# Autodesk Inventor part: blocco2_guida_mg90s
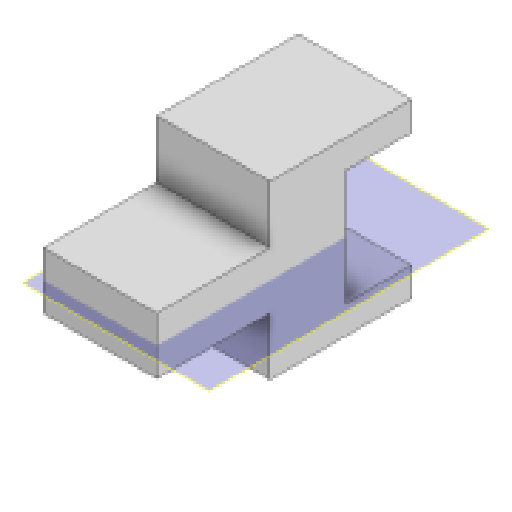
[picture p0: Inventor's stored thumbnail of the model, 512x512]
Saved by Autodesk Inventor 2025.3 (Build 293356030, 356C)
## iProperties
Created: 2026-04
Part Number: blocco2_guida_mg90s
Material: Generico
Document SubType Name: Modeling
Designer: R5800u
Density: 1 g/cm^3
Appearance: Default
Author: R5800u
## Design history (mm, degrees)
sketch "Schizzo1"
  geometry: L1 (-12.6, 12.35)-(-12.6, 0.15) reference; L2 (-2.271, 12.35)-(-2.271, 12.25) reference; L3 (-2.271, 12.25)-(-3.771, 12.25) reference; L4 (-3.771, 12.25)-(-3.771, 12.35) reference; L5 (-9.415, 12.35)-(-3.771, 12.35) reference; L6 (-9.415, 12.35)-(-9.415, 12.25) reference; L7 (-9.415, 12.25)-(-10.915, 12.25) reference; L8 (-10.915, 12.25)-(-10.915, 12.35) reference; L9 (-12.6, 12.35)-(-10.915, 12.35) reference; L10 (-12.6, 12.35)-(-12.6, 0.15) reference; L11 (5.4, 0.15)-(-12.6, 0.15) reference; L12 (5.4, 12.35)-(5.4, 0.15) reference; L13 (-2.271, 12.35)-(5.4, 12.35) reference; L14 (-12.6, 0.15)-(-0.6, 0.15); L15 (-0.6, 0.15)-(-0.6, 12.35); L16 (-0.6, 12.35)-(-12.6, 12.35); L17 (-12.6, 12.35)-(-12.6, 0.15); 12 further points
  constraints: 8 end point, 2 parallel, 1 horizontal, 1 perpendicular
  dimensions: "d0" = 12.2 distance of L15.end L14.end; "d12" = 12 distance of L1.end L14.end
extrude "Estrusione1" new body sketch "Schizzo1" distance "d1" = 8; taper "d2" = 0 deg
sketch "Schizzo3"
  geometry: L1 (-12.6, 12.35)-(-12.6, 0.15) reference; L2 (-12.6, 6.25)-(-3.6, 6.25); L3 (-12.6, 3.25)-(5.4, 3.25); L4 (5.4, 3.25)-(5.4, 9.25); L5 (5.4, 9.25)-(-12.6, 9.25); L6 (-12.6, 9.25)-(-12.6, 3.25); L7 (-0.6, 0.15)-(-0.6, 12.35) reference; 4 further points
  constraints: 10 end point, 2 parallel, 1 horizontal, 1 midpoint, 1 perpendicular, 1 point on line, 1 other
  dimensions: "d11" = 6 distance of L4.end L3.end
extrude "Estrusione2" join sketch "Schizzo3" distance "d13" = 12; taper "d14" = 0 deg
sketch "Schizzo5"
  geometry: L1 (0, 0)-(12, 0) reference; L2 (0, 8)-(12, 8) reference; L3 (0, 0)-(0, 8) reference; L4 (0, 8)-(12, 8); L5 (12, 8)-(12, -7); L6 (12, -7)-(0, -7); L7 (0, -7)-(0, 8); L8 (12, 0)-(12, 8) reference; L9 (12, 0)-(12, 8) reference; 6 further points
  constraints: 8 end point, 2 parallel, 1 horizontal, 1 midpoint, 1 perpendicular, 1 point on line
  dimensions: "d22" = 15 distance of L4.end L5.end
extrude "Estrusione3" join sketch "Schizzo5" distance "d23" = 3; taper "d24" = 0 deg
node "Piano di lavoro1"
mirror "Speculare1"
sketch "Schizzo6"
  geometry: L1 (20, -3.1)-(20, 9.1) reference; L2 (27, 9.1)-(20, 9.1) reference; L3 (27, 9.1)-(27, 12.1) reference; L4 (27, 12.1)-(12, 12.1) reference; L5 (12, 6)-(12, 12.1) reference; L6 (12, 6)-(0, 6) reference; L7 (0, 0)-(0, 6) reference; L8 (12, 0)-(0, 0) reference; L9 (12, 0)-(12, -6.1) reference; L10 (27, -6.1)-(12, -6.1) reference; L11 (27, -3.1)-(27, -6.1) reference; L12 (27, -3.1)-(20, -3.1) reference; L13 (12, 0)-(12, 6); 1 further point
  constraints: 2 end point, 1 vertical
  node "Linea chiusa proiettata2"
node "Piano di lavoro2"
extrude "Estrusione4" join sketch "Schizzo6" stored distance "d25" = 12; taper "d26" = 0 deg
chamfer "Smusso1" distance "d27" = 6; stored, may be unused: second distance "d28" = 2, angle "d29" = 45 deg
chamfer "Smusso2" distance "d30" = 2; stored, may be unused: second distance "d31" = 2, angle "d32" = 45 deg
sketch "Schizzo7"
  geometry: A1 r 1.5 centre (-2.4, 6.1) between (-3.775, 5.5) and (-3.775, 6.7) reference; 1 further point
hole "Foro3" sketch "Schizzo7" at (-2.4, 6.1) diameter "d33" = 2.9; stored, may be unused: countersink angle "d37" = 90 deg, drill point angle "d39" = 118 deg; dims "d34" = 6, "d35" = 4.5, "d36" = 12, "d38" = 8
node "Solido1"
node "Riferimento1"
node "Riferimento2"
node "Linea chiusa proiettata1"
node "Riferimento5"
